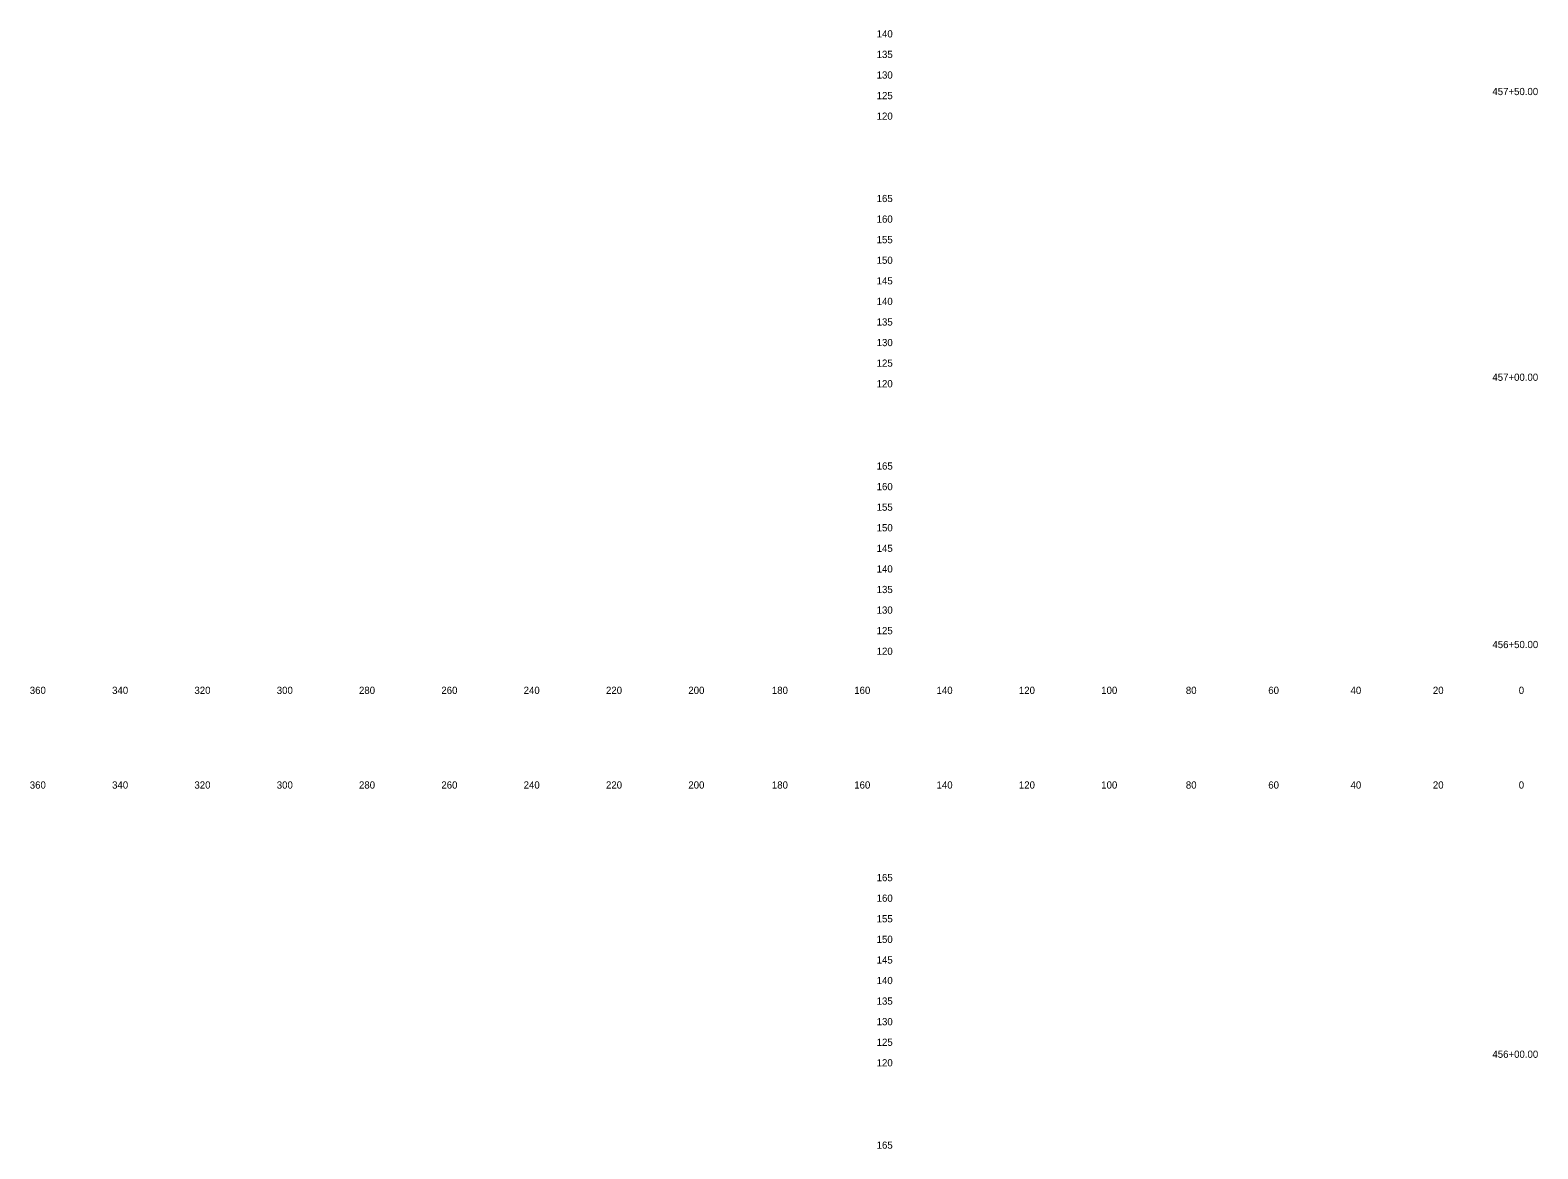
# Model space of a CAD drawing. Extents: x 21281 to 22024, y 6472 to 15198.
# Drawn here: x 21280.5 to 21646.7, y 7284.8 to 7556.6 of the extents above; entities that cross this region are included whole.
import ezdxf

# ---------------------------------------------------------------- set-up
doc = ezdxf.new("R2010")
doc.units = 0
for name, color, linetype in [('Draft_XS_Grid', 7, 'Continuous'), ('Draft_XS_Text', 7, 'Continuous'), ('SLOPE_STAKES_FILL', 7, 'Continuous')]:
    doc.layers.add(name, color=color, linetype=linetype)

msp = doc.modelspace()

# ---------------------------------------------------------------- texts
at = {"layer": 'Draft_XS_Grid'}
for s, p in [('  140  ', (21484.84, 7554.84)), ('  135  ', (21484.84, 7549.84)), ('  130  ', (21484.84, 7544.84)), ('  125  ', (21484.84, 7539.84)), ('  120  ', (21484.84, 7534.84)), ('  165  ', (21484.84, 7514.84)), ('  160  ', (21484.84, 7509.84)), ('  155  ', (21484.84, 7504.84)), ('  150  ', (21484.84, 7499.84)), ('  145  ', (21484.84, 7494.84)), ('  140  ', (21484.84, 7489.84)), ('  135  ', (21484.84, 7484.84)), ('  130  ', (21484.84, 7479.84)), ('  125  ', (21484.84, 7474.84)), ('  120  ', (21484.84, 7469.84)), ('  165  ', (21484.84, 7449.84)), ('  160  ', (21484.84, 7444.84)), ('  155  ', (21484.84, 7439.84)), ('  150  ', (21484.84, 7434.84)), ('  145  ', (21484.84, 7429.84)), ('  140  ', (21484.84, 7424.84)), ('  135  ', (21484.84, 7419.84)), ('  130  ', (21484.84, 7414.84)), ('  125  ', (21484.84, 7409.84)), ('  120  ', (21484.84, 7404.84)), ('  165  ', (21484.84, 7349.84)), ('  160  ', (21484.84, 7344.84)), ('  155  ', (21484.84, 7339.84)), ('  150  ', (21484.84, 7334.84)), ('  145  ', (21484.84, 7329.84)), ('  140  ', (21484.84, 7324.84)), ('  135  ', (21484.84, 7319.84)), ('  130  ', (21484.84, 7314.84)), ('  125  ', (21484.84, 7309.84)), ('  120  ', (21484.84, 7304.84)), ('  165  ', (21484.84, 7284.84))]:
    msp.add_text(s, height=1.75, dxfattribs=at).set_placement(p)
at = {"layer": 'Draft_XS_Text'}
for s, p in [('  360  ', (21279.14, 7395.34)), ('  340  ', (21299.13, 7395.34)), ('  320  ', (21319.13, 7395.34)), ('  300  ', (21339.13, 7395.34)), ('  280  ', (21359.1, 7395.34)), ('  260  ', (21379.11, 7395.34)), ('  240  ', (21399.1, 7395.34)), ('  220  ', (21419.1, 7395.34)), ('  200  ', (21439.1, 7395.34)), ('  180  ', (21459.39, 7395.34)), ('  160  ', (21479.4, 7395.34)), ('  140  ', (21499.39, 7395.34)), ('  120  ', (21519.39, 7395.34)), ('  100  ', (21539.39, 7395.34)), ('  80  ', (21559.95, 7395.34)), ('  60  ', (21579.97, 7395.34)), ('  40  ', (21599.95, 7395.34)), ('  20  ', (21619.95, 7395.34)), ('  0  ', (21640.81, 7395.34)), ('  0  ', (21640.81, 7395.34)), ('  360  ', (21279.14, 7372.34)), ('  340  ', (21299.13, 7372.34)), ('  320  ', (21319.13, 7372.34)), ('  300  ', (21339.13, 7372.34)), ('  280  ', (21359.1, 7372.34)), ('  260  ', (21379.11, 7372.34)), ('  240  ', (21399.1, 7372.34)), ('  220  ', (21419.1, 7372.34)), ('  200  ', (21439.1, 7372.34)), ('  180  ', (21459.39, 7372.34)), ('  160  ', (21479.4, 7372.34)), ('  140  ', (21499.39, 7372.34)), ('  120  ', (21519.39, 7372.34)), ('  100  ', (21539.39, 7372.34)), ('  80  ', (21559.95, 7372.34)), ('  60  ', (21579.97, 7372.34)), ('  40  ', (21599.95, 7372.34)), ('  20  ', (21619.95, 7372.34)), ('  0  ', (21640.81, 7372.34)), ('  0  ', (21640.81, 7372.34))]:
    msp.add_text(s, height=1.75, dxfattribs=at).set_placement(p)
at = {"layer": 'SLOPE_STAKES_FILL'}
for s, p in [('  457+50.00  ', (21634.4, 7540.83)), ('  457+00.00  ', (21634.4, 7471.41)), ('  456+50.00  ', (21634.41, 7406.47)), ('  456+00.00  ', (21634.41, 7306.93))]:
    msp.add_text(s, height=1.75, dxfattribs=at).set_placement(p)

doc.saveas('drawing.dxf')
